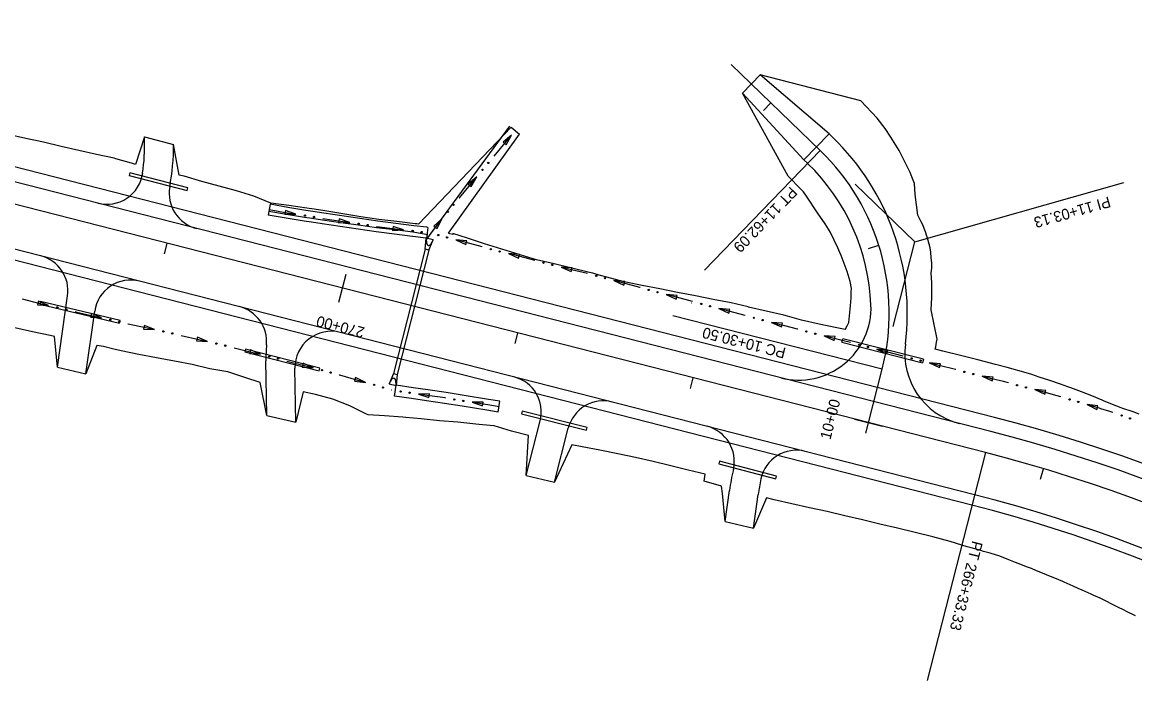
# Model space of a CAD drawing. Extents: x 948761 to 996004, y 1858548 to 1925175.
# Drawn here: x 963661 to 964276, y 1900633 to 1901004 of the extents above; entities that cross this region are included whole.
import ezdxf

# ---------------------------------------------------------------- set-up
doc = ezdxf.new("R2010")
doc.units = 0
for name, color, linetype in [('43', 7, 'Continuous'), ('62', 7, 'Continuous'), ('R_Drainage', 7, 'Continuous'), ('R_Horz Alg', 7, 'Continuous'), ('R_Horz Alg Annot', 7, 'Continuous'), ('R_Proposed Const Limits', 7, 'Continuous'), ('R_Proposed Road', 7, 'Continuous')]:
    doc.layers.add(name, color=color, linetype=linetype)

msp = doc.modelspace()

# ---------------------------------------------------------------- linework, layer by layer
at = {"layer": '43'}
for p, q in [((963884, 1900878.33), (963884.55, 1900884.5)), ((963888.43, 1900883.51), (963884.55, 1900884.5)), ((963884.55, 1900884.5), (963884.72, 1900881.57)), ((963885.94, 1900877.83), (963888.43, 1900883.51)), ((963888.43, 1900883.51), (963886.87, 1900881.02)), ((963885.94, 1900877.83), (963884, 1900878.33)), ((963866.45, 1900809.69), (963863.97, 1900804.01)), ((963866.45, 1900809.69), (963868.39, 1900809.19)), ((963868.39, 1900809.19), (963867.84, 1900803.01)), ((963863.97, 1900804.01), (963865.53, 1900806.5)), ((963863.97, 1900804.01), (963867.84, 1900803.01)), ((963867.84, 1900803.01), (963867.68, 1900805.95))]:
    msp.add_line(p, q, dxfattribs=at)
for centre, start, end in [((963885.88, 1900881.63), 183.17226, 328.11242), ((963866.52, 1900805.89), 3.17226, 148.11242)]:
    msp.add_arc(centre, 1.17, start, end, dxfattribs=at)
at = {"layer": '62'}
for p, q in [((963884.31, 1900883.13), (963930.72, 1900946.32)), ((963931.67, 1900941.35), (963927.01, 1900937.42)), ((963927.01, 1900937.42), (963928.64, 1900936.06)), ((963928.64, 1900936.06), (963931.67, 1900941.35)), ((963912.43, 1900918.28), (963907.77, 1900914.35)), ((963909.4, 1900912.99), (963912.43, 1900918.28)), ((963907.77, 1900914.35), (963909.4, 1900912.99)), ((963798.24, 1900903.16), (963797.22, 1900897.25)), ((963806.78, 1900899.71), (963806.43, 1900897.63)), ((963812.52, 1900897.69), (963806.78, 1900899.71)), ((963806.43, 1900897.63), (963812.52, 1900897.69)), ((963836.44, 1900895.06), (963836.12, 1900892.97)), ((963836.12, 1900892.97), (963842.21, 1900893.11)), ((963842.21, 1900893.11), (963836.44, 1900895.06)), ((963893.19, 1900895.22), (963888.78, 1900891.01)), ((963890.49, 1900889.75), (963893.19, 1900895.22)), ((963866.15, 1900890.84), (963865.88, 1900888.75)), ((963865.88, 1900888.75), (963871.97, 1900889.03)), ((963871.97, 1900889.03), (963866.15, 1900890.84)), ((963885.41, 1900890.42), (963884.71, 1900884.46)), ((963888.78, 1900891.01), (963890.49, 1900889.75)), ((963900.89, 1900883.62), (963906.4, 1900881.03)), ((963906.95, 1900883.07), (963900.89, 1900883.62)), ((963906.4, 1900881.03), (963906.95, 1900883.07)), ((963929.91, 1900875.9), (963935.47, 1900873.39)), ((963935.99, 1900875.44), (963929.91, 1900875.9)), ((963935.47, 1900873.39), (963935.99, 1900875.44)), ((963959.03, 1900868.5), (963964.58, 1900866)), ((963965.1, 1900868.05), (963959.03, 1900868.5)), ((963964.58, 1900866), (963965.1, 1900868.05)), ((963988.13, 1900861.1), (963993.65, 1900858.5)), ((963994.2, 1900860.55), (963988.13, 1900861.1)), ((963993.65, 1900858.5), (963994.2, 1900860.55)), ((963670.24, 1900849.71), (963669.75, 1900847.65)), ((963675.83, 1900847.29), (963670.24, 1900849.71)), ((964017.14, 1900853.3), (964022.67, 1900850.74)), ((964023.21, 1900852.78), (964017.14, 1900853.3)), ((964022.67, 1900850.74), (964023.21, 1900852.78)), ((963669.75, 1900847.65), (963675.83, 1900847.29)), ((964046.18, 1900845.6), (964051.71, 1900843.04)), ((964052.25, 1900845.09), (964046.18, 1900845.6)), ((964051.71, 1900843.04), (964052.25, 1900845.09)), ((963699.48, 1900842.87), (963699, 1900840.81)), ((963699, 1900840.81), (963705.09, 1900840.49)), ((963705.09, 1900840.49), (963699.48, 1900842.87)), ((964075.23, 1900837.95), (964080.76, 1900835.4)), ((964081.3, 1900837.44), (964075.23, 1900837.95)), ((964080.76, 1900835.4), (964081.3, 1900837.44)), ((963728.77, 1900836.27), (963728.32, 1900834.2)), ((963728.32, 1900834.2), (963734.41, 1900833.96)), ((963734.41, 1900833.96), (963728.77, 1900836.27)), ((963758.13, 1900829.81), (963757.63, 1900827.75)), ((963757.63, 1900827.75), (963763.71, 1900827.38)), ((963763.71, 1900827.38), (963758.13, 1900829.81)), ((964104.32, 1900830.49), (964109.88, 1900828)), ((964110.4, 1900830.05), (964104.32, 1900830.49)), ((964109.88, 1900828), (964110.4, 1900830.05)), ((963787.34, 1900822.8), (963786.83, 1900820.74)), ((963786.83, 1900820.74), (963792.91, 1900820.33)), ((963792.91, 1900820.33), (963787.34, 1900822.8)), ((964133.44, 1900823.13), (964138.99, 1900820.62)), ((964139.52, 1900822.67), (964133.44, 1900823.13)), ((964138.99, 1900820.62), (964139.52, 1900822.67)), ((963816.45, 1900815.33), (963815.91, 1900813.28)), ((963815.91, 1900813.28), (963821.99, 1900812.79)), ((963821.99, 1900812.79), (963816.45, 1900815.33)), ((964162.52, 1900815.58), (964168.06, 1900813.05)), ((964168.59, 1900815.1), (964162.52, 1900815.58)), ((964168.06, 1900813.05), (964168.59, 1900815.1)), ((963845.45, 1900807.42), (963844.87, 1900805.38)), ((963850.93, 1900804.75), (963845.45, 1900807.42)), ((964191.63, 1900808.18), (964197.2, 1900805.71)), ((964197.71, 1900807.76), (964191.63, 1900808.18)), ((964197.2, 1900805.71), (964197.71, 1900807.76)), ((963844.87, 1900805.38), (963850.93, 1900804.75)), ((963866.94, 1900797.26), (963867.91, 1900803.18)), ((964220.75, 1900800.8), (964226.27, 1900798.23)), ((964226.82, 1900800.27), (964220.75, 1900800.8)), ((963886.33, 1900798.51), (963880.24, 1900798.34)), ((963880.24, 1900798.34), (963886.02, 1900796.42)), ((963886.02, 1900796.42), (963886.33, 1900798.51)), ((963924.25, 1900788.41), (963925.22, 1900794.33)), ((964226.27, 1900798.23), (964226.82, 1900800.27)), ((963916.02, 1900793.87), (963909.93, 1900793.79)), ((963909.93, 1900793.79), (963915.68, 1900791.78)), ((963915.68, 1900791.78), (963916.02, 1900793.87)), ((964249.64, 1900792.61), (964255.07, 1900789.83)), ((964255.69, 1900791.86), (964249.64, 1900792.61)), ((964255.07, 1900789.83), (964255.69, 1900791.86))]:
    msp.add_line(p, q, dxfattribs=at)
for points in [[(963922.06, 1900929.83), (963931.67, 1900941.35)], [(963922.03, 1900929.8), (963922.06, 1900929.83)], [(963902.82, 1900906.76), (963912.43, 1900918.28)], [(963902.8, 1900906.73), (963902.82, 1900906.76)], [(963885.4, 1900886.39), (963878.13, 1900887.66), (963877.13, 1900887.77), (963867.12, 1900888.99), (963857.11, 1900890.22), (963847.14, 1900891.57), (963837.18, 1900893.01), (963827.23, 1900894.46), (963821.26, 1900895.32), (963817.28, 1900895.9), (963807.36, 1900897.48), (963797.46, 1900899.12)], [(963797.73, 1900900.21), (963807.62, 1900898.5), (963812.52, 1900897.69)], [(963885.41, 1900890.42), (963884.9, 1900890.48), (963877.73, 1900891.31), (963877.64, 1900891.32), (963867.67, 1900892.61), (963857.69, 1900893.89), (963847.77, 1900895.31), (963827.91, 1900898.31), (963821.94, 1900899.22), (963817.99, 1900899.82), (963808.12, 1900901.46), (963798.25, 1900903.16)], [(963884.71, 1900884.46), (963884.2, 1900884.52), (963877.04, 1900885.35), (963876.91, 1900885.37), (963866.9, 1900886.66), (963856.89, 1900887.95), (963846.89, 1900889.37), (963827.01, 1900892.38), (963821.05, 1900893.29), (963817.05, 1900893.89), (963807.12, 1900895.54), (963797.22, 1900897.25)], [(963827.34, 1900895.37), (963827.38, 1900895.36)], [(963827.38, 1900895.36), (963827.46, 1900895.35), (963837.39, 1900893.84), (963842.21, 1900893.11)], [(963887.28, 1900887.18), (963893.19, 1900895.22)], [(963857.05, 1900890.95), (963857.09, 1900890.95)], [(963857.09, 1900890.95), (963857.29, 1900890.92), (963867.28, 1900889.63), (963871.97, 1900889.03)], [(963886.86, 1900887.23), (963886.9, 1900887.22)], [(963886.9, 1900887.22), (963887.3, 1900887.18)], [(963915.36, 1900879.69), (963906.63, 1900882.06), (963900.89, 1900883.62)], [(963915.4, 1900879.68), (963915.36, 1900879.69)], [(963944.45, 1900872.2), (963939.21, 1900873.53), (963935.65, 1900874.44), (963929.91, 1900875.9)], [(963944.49, 1900872.19), (963944.45, 1900872.2)], [(963973.6, 1900864.97), (963964.73, 1900867.05), (963959.03, 1900868.5)], [(963973.64, 1900864.96), (963973.6, 1900864.97)], [(964002.61, 1900857.17), (963993.78, 1900859.57), (963988.13, 1900861.1)], [(964002.65, 1900857.16), (964002.61, 1900857.17)], [(963661.28, 1900850.95), (963670.96, 1900848.45), (963675.83, 1900847.29)], [(964031.64, 1900849.45), (964022.76, 1900851.81), (964017.14, 1900853.3)], [(963690.44, 1900843.88), (963690.44, 1900843.88), (963690.47, 1900843.88)], [(963690.47, 1900843.87), (963691.41, 1900843.66), (963700.18, 1900841.62), (963705.09, 1900840.49)], [(964031.2, 1900848.54), (964031.16, 1900848.55)], [(964031.68, 1900849.44), (964031.64, 1900849.45)], [(964060.68, 1900841.77), (964051.76, 1900844.12), (964046.18, 1900845.6)], [(964060.72, 1900841.76), (964060.68, 1900841.77)], [(964089.74, 1900834.17), (964082.71, 1900835.98), (964080.77, 1900836.49), (964075.23, 1900837.95)], [(963719.71, 1900837.16), (963719.75, 1900837.15)], [(963719.75, 1900837.15), (963729.46, 1900835.04), (963734.41, 1900833.96)], [(964089.78, 1900834.16), (964089.74, 1900834.17)], [(963749.06, 1900830.77), (963749.1, 1900830.76)], [(963749.1, 1900830.76), (963758.77, 1900828.56), (963763.71, 1900827.38)], [(964118.87, 1900826.83), (964115.06, 1900827.79), (964109.85, 1900829.1), (964104.32, 1900830.49)], [(964118.91, 1900826.82), (964118.87, 1900826.83)], [(963778.3, 1900823.88), (963778.33, 1900823.87)], [(963778.33, 1900823.87), (963787.95, 1900821.56), (963792.91, 1900820.33)], [(964147.96, 1900819.36), (964138.93, 1900821.73), (964133.44, 1900823.13)], [(964148, 1900819.36), (964147.96, 1900819.36)], [(963807.44, 1900816.6), (963807.48, 1900816.59)], [(963807.48, 1900816.59), (963817, 1900814.09), (963821.99, 1900812.79)], [(964177.05, 1900811.86), (964167.96, 1900814.17), (964162.52, 1900815.58)], [(963836.47, 1900808.89), (963836.51, 1900808.88)], [(963836.51, 1900808.88), (963845.94, 1900806.18), (963850.93, 1900804.75)], [(964177.09, 1900811.85), (964177.05, 1900811.86)], [(964206.18, 1900804.52), (964203.51, 1900805.2), (964197.05, 1900806.84), (964191.63, 1900808.18)], [(963865.36, 1900800.52), (963865.15, 1900800.55)], [(963865.4, 1900800.51), (963865.36, 1900800.52)], [(963925.22, 1900794.33), (963918.95, 1900795.35), (963905.39, 1900797.58), (963895.44, 1900799.13), (963885.48, 1900800.6), (963877.2, 1900801.82), (963867.91, 1900803.18)], [(964206.21, 1900804.51), (964206.18, 1900804.51)], [(964235.21, 1900796.84), (964233.07, 1900797.45), (964227.18, 1900799.07), (964227.18, 1900799.08), (964221.27, 1900800.66), (964220.75, 1900800.8)], [(963924.25, 1900788.41), (963917.97, 1900789.43), (963904.44, 1900791.65), (963894.54, 1900793.2), (963884.61, 1900794.67), (963876.33, 1900795.89), (963866.94, 1900797.26)], [(963895.08, 1900796.15), (963894.99, 1900796.17), (963885.05, 1900797.63), (963880.24, 1900798.34)], [(963895.11, 1900796.15), (963895.08, 1900796.15)], [(964235.25, 1900796.83), (964235.21, 1900796.84)], [(963924.73, 1900791.37), (963918.46, 1900792.39), (963914.83, 1900792.99), (963909.93, 1900793.79)], [(964263.95, 1900788.1), (964262.33, 1900788.64), (964257.36, 1900790.23), (964256.51, 1900790.5), (964250.67, 1900792.29), (964249.64, 1900792.6)], [(964263.99, 1900788.09), (964263.95, 1900788.1)]]:
    msp.add_lwpolyline(points, dxfattribs=at)
for centre in [(963918.81, 1900926), (963915.61, 1900922.15), (963896.37, 1900899.08), (963899.58, 1900902.93), (963817.47, 1900896.9), (963822.42, 1900896.15), (963847.16, 1900892.4), (963852.12, 1900891.69), (963876.94, 1900888.43), (963881.91, 1900887.84), (963891.19, 1900886.13), (963896.04, 1900884.87), (963920.21, 1900878.37), (963925.05, 1900877.1), (963949.31, 1900870.93), (963954.16, 1900869.69), (963978.46, 1900863.67), (963983.29, 1900862.37), (964007.46, 1900855.84), (964012.3, 1900854.55), (963680.71, 1900846.17), (963685.59, 1900845.04), (964036.49, 1900848.13), (964041.33, 1900846.84), (963709.97, 1900839.39), (963714.86, 1900838.29), (964065.53, 1900840.46), (964070.37, 1900839.19), (963739.3, 1900832.93), (963744.2, 1900831.87), (964094.6, 1900832.91), (964099.46, 1900831.68), (963768.59, 1900826.25), (963773.46, 1900825.08), (964123.73, 1900825.56), (963797.78, 1900819.17), (964128.59, 1900824.34), (963802.63, 1900817.9), (964152.81, 1900818.06), (964157.66, 1900816.79), (963826.84, 1900811.55), (963831.67, 1900810.23), (964181.91, 1900810.59), (964186.76, 1900809.36), (963855.75, 1900803.4), (963860.55, 1900801.96), (964211.03, 1900803.24), (964215.89, 1900802.02), (963870.32, 1900799.76), (963875.28, 1900799.04), (963900.03, 1900795.34), (963904.98, 1900794.57), (964240.03, 1900795.41), (964244.84, 1900794), (964268.71, 1900786.5), (964273.46, 1900784.89)]:
    msp.add_circle(centre, 0.375, dxfattribs=at)
at = {"layer": 'R_Drainage'}
for p, q in [((963720.74, 1900920.5), (963720.37, 1900919.04)), ((963720.37, 1900919.04), (963752.41, 1900910.85)), ((963752.78, 1900912.3), (963720.74, 1900920.5)), ((963752.41, 1900910.85), (963752.78, 1900912.3)), ((963884, 1900878.33), (963866.45, 1900809.69)), ((963885.94, 1900877.83), (963868.39, 1900809.19)), ((963671.38, 1900849.54), (963671.03, 1900848.09)), ((963715.45, 1900838.99), (963671.38, 1900849.54)), ((963671.03, 1900848.09), (963715.1, 1900837.53)), ((963715.1, 1900837.53), (963715.45, 1900838.99)), ((964114.18, 1900826.99), (964114.67, 1900828.93)), ((964114.18, 1900826.99), (964158.75, 1900815.64)), ((964159.25, 1900817.58), (964114.67, 1900828.93)), ((963784.68, 1900823.21), (963784.31, 1900821.75)), ((963784.31, 1900821.75), (963825.26, 1900811.18)), ((963825.63, 1900812.64), (963784.68, 1900823.21)), ((964159.25, 1900817.58), (964158.75, 1900815.64)), ((963825.26, 1900811.18), (963825.63, 1900812.64)), ((963937.51, 1900788.87), (963937.15, 1900787.42)), ((963973.45, 1900779.87), (963937.51, 1900788.87)), ((963937.15, 1900787.42), (963973.08, 1900778.41)), ((963973.08, 1900778.41), (963973.45, 1900779.87)), ((964046.53, 1900761.26), (964046.14, 1900759.81)), ((964046.14, 1900759.81), (964077.61, 1900751.48)), ((964077.99, 1900752.93), (964046.53, 1900761.26)), ((964077.61, 1900751.48), (964077.99, 1900752.93))]:
    msp.add_line(p, q, dxfattribs=at)
at = {"layer": 'R_Horz Alg'}
for p, q in [((964193.49, 1900766), (963339.31, 1900984.4)), ((964102.23, 1900932.9), (964053.04, 1900980.45)), ((964128.9, 1900782.51), (964136.46, 1900812.06))]:
    msp.add_line(p, q, dxfattribs=at)
for centre, radius, start, end in [((964015.35, 1900843.03), 125, 345.65786, 45.97201), ((963983.23, 1899943.63), 848.83, 24.09145, 75.65786)]:
    msp.add_arc(centre, radius, start, end, dxfattribs=at)
at = {"layer": 'R_Horz Alg Annot'}
for p in [(964121.46, 1900914.31), (964142.5, 1900835.68)]:
    msp.add_line(p, (964154.45, 1900882.43), dxfattribs=at)
for points in [[(964070.8, 1900954.94), (964074.97, 1900959.25)], [(964102.23, 1900932.9), (964038.26, 1900866.72)], [(964154.45, 1900882.43), (964269.91, 1900915.13)], [(963739.88, 1900875.79), (963741.37, 1900881.6)], [(964128.84, 1900878.84), (964134.56, 1900880.65)], [(963836.27, 1900849.08), (963840.23, 1900864.58)], [(964136.46, 1900812.06), (964020.84, 1900841.63)], [(963933.65, 1900826.24), (963935.13, 1900832.06)], [(964030.53, 1900801.47), (964032.02, 1900807.29)], [(964121.15, 1900784.5), (964136.65, 1900780.53)], [(964127.42, 1900776.7), (964128.9, 1900782.51)], [(964193.49, 1900766), (964161.29, 1900640.05)], [(964223.9, 1900751.36), (964225.61, 1900757.11)]]:
    msp.add_lwpolyline(points, dxfattribs=at)
at = {"layer": 'R_Proposed Const Limits'}
msp.add_line((963896.9, 1900887.17), (963936.1, 1900941.98), dxfattribs=at)
for points in [[(964165.78, 1900823.1), (964166.1, 1900824.35), (964166.54, 1900827.08), (964166.8, 1900828.7), (964163.44, 1900844.93), (964163.96, 1900851.69), (964163.98, 1900854.4), (964163.88, 1900859.83), (964163.58, 1900865.28), (964163.88, 1900867.83), (964163.86, 1900868.34), (964163.83, 1900870.86), (964163.59, 1900873.6), (964163.26, 1900876.67), (964162.95, 1900879.1), (964161.85, 1900883.09), (964160.34, 1900887.87), (964158.72, 1900892.21), (964158.07, 1900893.44), (964156.09, 1900897.09), (964154.74, 1900908.54), (964154.34, 1900914.62), (964152.49, 1900919.18), (964151.92, 1900920.69), (964145.84, 1900932.82), (964141.32, 1900940.22), (964138.08, 1900945.04), (964133.67, 1900950.81), (964124.65, 1900960.29), (964069.05, 1900974.71)], [(964119.41, 1900856.72), (964118.81, 1900860.48), (964117.14, 1900865.96), (964113.82, 1900874.82), (964113.11, 1900876.56), (964111.99, 1900879.15), (964107.87, 1900887.54), (964106.72, 1900889.52), (964104.95, 1900892.31), (964100.73, 1900898.41), (964094.58, 1900907.68), (964092.92, 1900909.97), (964091.76, 1900911.33), (964084.52, 1900918.78), (964059.32, 1900964.64)], [(963728.86, 1900940.37), (963723.94, 1900925.22), (963721.72, 1900925.87), (963713.07, 1900928.35), (963712.09, 1900928.56), (963702.3, 1900930.64), (963692.55, 1900932.86), (963682.82, 1900935.18), (963673.07, 1900937.42), (963663.3, 1900939.59), (963653.55, 1900941.81)], [(963880.2, 1900892.13), (963931.49, 1900945.83), (963936.1, 1900941.98)], [(963798.63, 1900903.72), (963789.33, 1900907.71), (963779.75, 1900910.62), (963770.08, 1900913.18), (963760.45, 1900915.85), (963750.83, 1900918.62), (963747.95, 1900919.3), (963744.92, 1900936.29)], [(963880.2, 1900892.13), (963879.33, 1900892.33), (963878.32, 1900892.44), (963868.32, 1900893.68), (963858.29, 1900894.82), (963848.35, 1900896.31), (963838.44, 1900897.92), (963828.53, 1900899.54), (963822.57, 1900900.47), (963818.6, 1900901.06), (963808.63, 1900902.46), (963798.63, 1900903.72)], [(964115.98, 1900833.93), (964111.34, 1900834.95), (964101.56, 1900837.04), (964091.78, 1900839.16), (964084.06, 1900841.29), (964082.16, 1900841.92), (964072.4, 1900844.09), (964062.65, 1900846.36), (964062.34, 1900846.46), (964052.95, 1900848.76), (964043.1, 1900850.65), (964033.28, 1900852.58), (964023.44, 1900854.46), (964013.62, 1900856.44), (964003.78, 1900858.33), (963993.96, 1900860.27), (963984.31, 1900862.9), (963980.14, 1900864.07), (963976.6, 1900865.05), (963974.67, 1900865.58), (963964.95, 1900867.91), (963955.22, 1900870.23), (963945.5, 1900872.58), (963939.43, 1900874.4), (963935.92, 1900875.49), (963926.33, 1900878.37), (963916.78, 1900881.38), (963907.25, 1900884.46), (963899.29, 1900886.97), (963899.17, 1900886.54), (963897.56, 1900886.94), (963896.9, 1900887.17)], [(964115.98, 1900833.93), (964117.09, 1900836.12), (964118, 1900837.82), (964118.22, 1900839.68), (964118.41, 1900841.55), (964118.41, 1900841.55), (964118.57, 1900843.42), (964118.79, 1900845.3), (964118.97, 1900847.18), (964119.12, 1900849.08), (964119.17, 1900849.86), (964119.24, 1900850.98), (964119.33, 1900852.89), (964119.39, 1900854.8), (964119.41, 1900856.72)], [(963680.81, 1900813.19), (963679.12, 1900830.15), (963676.76, 1900830.75), (963666.95, 1900832.76), (963657.21, 1900835.01), (963647.46, 1900837.26), (963637.87, 1900840.13), (963628.2, 1900842.66), (963625.01, 1900843.09), (963616.22, 1900828.13)], [(963796.41, 1900786.45), (963792.78, 1900804.75), (963784.36, 1900807.54), (963774.81, 1900810.56), (963764.94, 1900812.31), (963755.2, 1900814.59), (963745.36, 1900816.49), (963735.51, 1900818.33), (963725.66, 1900820.16), (963715.88, 1900822.29), (963711.98, 1900823.2), (963706.14, 1900824.55), (963702.53, 1900825.25), (963696.46, 1900809.57)], [(964278.54, 1900787.27), (964275.21, 1900788.47), (964269.4, 1900790.45), (964268.59, 1900790.72), (964263.64, 1900792.59), (964258.76, 1900794.54), (964257.93, 1900794.91), (964252.28, 1900797.41), (964249, 1900798.67), (964246.51, 1900799.59), (964240.72, 1900801.7), (964239.08, 1900802.29), (964234.92, 1900803.76), (964229.09, 1900805.78), (964229.09, 1900805.78), (964223.24, 1900807.76), (964219.07, 1900809.14), (964217.38, 1900809.69), (964211.45, 1900811.37), (964208.9, 1900812.04), (964205.49, 1900812.93), (964199.07, 1900814.74), (964189.37, 1900817.16), (964179.69, 1900819.67), (964169.99, 1900822.09), (964165.78, 1900823.1)], [(963931.59, 1900777.83), (963922.03, 1900780.81), (963915.66, 1900781.43), (963911.96, 1900781.79), (963901.88, 1900782.75), (963891.79, 1900783.63), (963881.71, 1900784.58), (963873.3, 1900785.31), (963873.32, 1900785.42), (963871.64, 1900785.58), (963861.49, 1900786.25), (963852.36, 1900786.86), (963851.43, 1900787.24), (963842.27, 1900791.79), (963832.89, 1900795.5), (963823.24, 1900798.12), (963816.49, 1900799.6), (963812.47, 1900782.74)], [(963939.77, 1900753.3), (963941.07, 1900775.46), (963931.59, 1900777.83)], [(964049.71, 1900727.87), (964048.16, 1900743.34), (964047.71, 1900747.55), (964038.06, 1900750.19), (964038.72, 1900754.08), (964029.32, 1900756.37), (964019.61, 1900758.75), (964009.88, 1900761.08), (964000.12, 1900763.28), (963990.33, 1900765.34), (963980.5, 1900767.26), (963970.68, 1900769.23), (963964.97, 1900770.34), (963955.36, 1900749.69)], [(964276.38, 1900675.78), (964271.53, 1900678.16), (964271.52, 1900678.16), (964271.5, 1900678.17), (964270.14, 1900678.87), (964266.65, 1900680.66), (964261.8, 1900683.1), (964261.77, 1900683.11), (964256.87, 1900685.51), (964253.34, 1900687.08), (964251.89, 1900687.72), (964246.92, 1900689.95), (964244.81, 1900690.91), (964241.94, 1900692.2), (964236.95, 1900694.42), (964236.25, 1900694.73), (964231.93, 1900696.6), (964227.62, 1900698.38), (964226.88, 1900698.67), (964221.81, 1900700.73), (964218.92, 1900701.9), (964216.74, 1900702.78), (964211.63, 1900704.74), (964210.18, 1900705.31), (964206.52, 1900706.74), (964201.41, 1900708.7), (964201.4, 1900708.7), (964196.19, 1900710.36), (964192.45, 1900711.45), (964190.94, 1900711.89), (964185.68, 1900713.37), (964183.43, 1900714.02), (964180.43, 1900714.93), (964174.03, 1900716.81), (964164.4, 1900719.52), (964154.68, 1900721.85), (964144.96, 1900724.23), (964135.22, 1900726.48), (964125.51, 1900728.9), (964115.75, 1900731.09), (964106.03, 1900733.43), (964096.24, 1900735.5), (964086.46, 1900737.64), (964076.74, 1900739.98), (964072.49, 1900741.02), (964065.36, 1900724.25)]]:
    msp.add_lwpolyline(points, dxfattribs=at)
at = {"layer": 'R_Proposed Road'}
for p, q in [((964198.44, 1900785.38), (963344.44, 1901003.73)), ((964196.46, 1900777.63), (963342.38, 1900996)), ((964069.05, 1900974.71), (964059.32, 1900964.64)), ((964107.09, 1900942.12), (964069.05, 1900974.71)), ((964187.54, 1900742.75), (963333.15, 1900961.2)), ((964059.32, 1900964.64), (964093.19, 1900927.74)), ((964186.06, 1900736.94), (963331.61, 1900955.4)), ((964107.09, 1900942.12), (964093.19, 1900927.74)), ((964107.09, 1900942.12), (964109.18, 1900940.09)), ((963728.86, 1900940.37), (963744.92, 1900936.29)), ((963728.89, 1900938.91), (963728.86, 1900940.37)), ((964093.19, 1900927.74), (964095.28, 1900925.71)), ((963680.81, 1900813.19), (963686.35, 1900852.52)), ((963696.46, 1900809.57), (963701.33, 1900844.15)), ((963680.81, 1900813.19), (963696.46, 1900809.57)), ((963796.41, 1900786.45), (963795.93, 1900816.74)), ((963812.47, 1900782.74), (963811.99, 1900812.69)), ((963796.41, 1900786.45), (963812.47, 1900782.74)), ((963939.77, 1900753.3), (963947.49, 1900783.48)), ((963955.36, 1900749.69), (963962.99, 1900779.52)), ((963939.77, 1900753.3), (963955.36, 1900749.69)), ((964049.71, 1900727.87), (964052.07, 1900744.98)), ((964065.36, 1900724.25), (964067.92, 1900742.8)), ((964049.71, 1900727.87), (964065.36, 1900724.25))]:
    msp.add_line(p, q, dxfattribs=at)
for centre, radius, start, end in [((963611.92, 1900936.45), 117, 352.12602, 1.20553), ((963611.92, 1900936.45), 133, 349.75337, 359.93209), ((964015.35, 1900843.03), 135, 352.71474, 45.97201), ((964015.35, 1900843.03), 115, 2.316, 45.97201), ((963708.01, 1900923.16), 20, 255.65786, 352.12602), ((963762.48, 1900909.23), 20, 169.75337, 255.65786), ((963666.55, 1900855.31), 20, 351.97882, 75.65786), ((963721.13, 1900841.36), 20, 75.65786, 171.97882), ((963776.33, 1900827.25), 20, 354.8836, 75.65786), ((964090.29, 1900846.06), 40, 255.65786, 2.316), ((963831.99, 1900813.01), 20, 75.65786, 180.91139), ((963878.92, 1900818.06), 83, 174.8836, 180.91139), ((964188.94, 1900820.84), 40, 172.71474, 255.65786), ((963928.11, 1900788.44), 20, 345.65786, 75.65786), ((963982.37, 1900774.56), 20, 75.65786, 165.65786), ((963983.23, 1899943.63), 868.83, 24.09145, 75.65786), ((964034.73, 1900761.18), 20, 347.03142, 75.65786), ((963983.23, 1899943.63), 860.83, 24.09145, 75.65786), ((964089, 1900747.3), 20, 75.65786, 167.82472), ((964183.82, 1900726.84), 133, 167.03142, 172.15955), ((964183.82, 1900726.84), 117, 167.82472, 172.15955), ((963983.23, 1899943.63), 824.83, 24.09145, 75.65786), ((963983.23, 1899943.63), 818.83, 24.09145, 75.65786)]:
    msp.add_arc(centre, radius, start, end, dxfattribs=at)

# ---------------------------------------------------------------- texts
at = {"layer": 'R_Horz Alg'}
for rotation, p in [(135.97201, (964053.69, 1900980.51)), (135.97201, (964102.88, 1900932.96)), (75.65786, (964136.84, 1900811.52)), (75.65786, (964129.28, 1900781.97)), (165.65786, (964193.61, 1900766.48)), (165.65786, (964193.61, 1900766.48))]:
    msp.add_text('+', height=1, rotation=rotation, dxfattribs=at).set_placement(p)
at = {"layer": 'R_Horz Alg Annot'}
for s, rotation, p in [('PT 11+62.09', 225.97201, (964085.82, 1900913.3)), ('PI 11+03.13', 195.81494, (964261.65, 1900907.59)), ('270+00', 165.65786, (963850.89, 1900835.02)), ('PC 10+30.50', 165.65786, (964083.65, 1900823.71)), ('10+00', 75.65786, (964107.83, 1900772.78)), ('PT 266+33.33', 255.65786, (964186.29, 1900717.65))]:
    msp.add_text(s, height=6, rotation=rotation, dxfattribs=at).set_placement(p)

doc.saveas('drawing.dxf')
